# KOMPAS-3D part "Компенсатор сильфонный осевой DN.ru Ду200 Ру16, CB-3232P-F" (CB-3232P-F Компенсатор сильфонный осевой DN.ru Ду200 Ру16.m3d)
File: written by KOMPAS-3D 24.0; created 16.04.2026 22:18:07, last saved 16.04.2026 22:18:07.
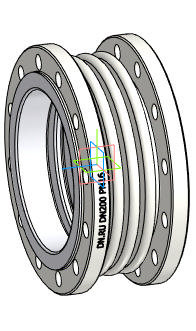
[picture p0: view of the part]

Document properties: Автор: DN.RU; Полное имя файла: D:\PROJECT CAD\DN.RU\..199(ACTUALE). CB-3232P-F Компенсатор сильфонный осевой DN.ru\Исходники\DN200\CB-3232P-F Компенсатор сильфонный осевой DN.ru Ду200 Ру16.m3d

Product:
- Body: Твердое тело1  | qty 1
    Масса: 24.92065
- Part/product: Компенсатор сильфонный осевой DN.ru Ду200 Ру16  | designation CB-3232P-F
    Масса: 19.6
    Раздел спецификации: Прочие изделия
    Комментарий: D140-02144
    Примечание: D140-02144
    additional columns: Типовые

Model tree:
1. Твердое тело1  (labels: Твердое тело1)

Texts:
  CB-3232P-F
